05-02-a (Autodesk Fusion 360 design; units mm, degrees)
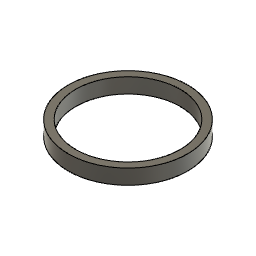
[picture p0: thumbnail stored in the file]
sketch "スケッチ" plane through (0, 0, 0) normal (0, 0, 1) x axis (1, 0, 0)
  line L1 (-7, -2) -> (-8, -2)
  line L2 (-7, 0) -> (-7, -2)
  line L3 (-8, 0) -> (-7, 0)
  line L4 (-8, -2) -> (-8, 0)
  line L5 (0, 22.5) -> (0, 1.75)
  point P1 (0, 0)
  point P4 (-7, 0)
  point P2 (-8, -2)
  point P3 (-7, -2)
  point P5 (-8, 0)
  horizontal L1
  vertical L2
  horizontal L3
  vertical L4
  horizontal P1 P4
  dimension "d1" distance P2 P3 = 1
  dimension "d2" distance P2 P5 = 2
  dimension "d3" = 16
revolve "回転" sketch "スケッチ" AlongAngle 360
